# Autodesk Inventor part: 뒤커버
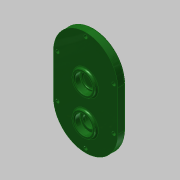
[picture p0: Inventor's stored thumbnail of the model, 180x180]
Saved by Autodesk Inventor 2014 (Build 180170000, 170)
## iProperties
Created: 2016-12
Part Number: 뒤커버
Material: 일반
Document SubType Name: Modeling
Designer: mduedu
Density: 1 g/cm^3
Appearance: 매끄러움 - 짙은 산림 녹색
Mass: 87.2081 g
Surface Area: 240.959 cm^2
Volume: 87.2081 cm^3
Author: mduedu
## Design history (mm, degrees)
sketch "스케치1"
  geometry: L1 (40, -25)-(40, 25); L2 (-40, 25)-(-40, -25); L3 (-40, -25)-(40, 25); L4 (40, -25)-(-40, 25); A1 r 40 centre (0, 25) between (40, 25) and (-40, 25); A2 r 40 centre (0, -25) between (-40, -25) and (40, -25); 1 further point
  constraints: 8 end point, 4 point on circle, 4 tangent, 2 centre point, 2 midpoint, 1 parallel, 1 vertical
  dimensions: "d0" = 130 dimension on A2 A1; "d2" = 80 distance between parallel lines of L1 L2
extrude "돌출1" new body sketch "스케치1" distance "d3" = 10; taper "d4" = 0 deg
sketch "스케치2"
  geometry: C1 r 14 at (0, 11); 1 further point
  constraints: 1 centre point, 1 vertical alignment
  dimensions: "d5" = 28 diameter of C1; "d6" = 11 distance of C1.centre point (0, 0)
extrude "돌출2" join sketch "스케치2" distance "d7" = 3; taper "d8" = 0 deg
sketch "스케치3"
  geometry: C1 r 14 at (0, -33.1); C2 r 14 at (0, 11) reference; 1 further point
  constraints: 1 centre point, 1 vertical alignment
  dimensions: "d9" = 28 diameter of C1; "d69" = 44.1 distance of C1.centre C2.centre
extrude "돌출3" join sketch "스케치3" distance "d11" = 3; taper "d12" = 0 deg
hole "구멍1" diameter "d15" = 22; stored, may be unused: countersink angle "d19" = 90 deg, drill point angle "d21" = 0 deg; dims "d13" = 10, "d14" = 10, "d16" = 6, "d17" = 4, "d18" = 2, "d20" = 7
hole "구멍2" diameter "d24" = 18; stored, may be unused: countersink angle "d28" = 90 deg, drill point angle "d30" = 0 deg; dims "d22" = 10, "d23" = 10, "d25" = 6, "d26" = 4, "d27" = 2, "d29" = 1
hole "구멍3" diameter "d33" = 22; stored, may be unused: countersink angle "d37" = 90 deg, drill point angle "d39" = 0 deg; dims "d31" = 10, "d32" = 10, "d34" = 6, "d35" = 4, "d36" = 2, "d38" = 7
sketch "스케치4"
  geometry: C1 r 14 at (0, -33.1) reference; C2 r 18 at (0, -33.1); 1 further point
  constraints: 1 centre point, 1 coincident
  dimensions: "d40" = 36 diameter of C2
extrude "돌출4" join sketch "스케치4" distance "d41" = 4; taper "d42" = 0 deg
hole "구멍4" diameter "d45" = 22; stored, may be unused: countersink angle "d49" = 90 deg, drill point angle "d51" = 0 deg; dims "d46" = 6, "d47" = 4, "d48" = 2, "d50" = 7.3, "d80" = 10, "d81" = 10
hole "구멍5" diameter "d54" = 15; stored, may be unused: countersink angle "d58" = 90 deg, drill point angle "d60" = 0 deg; dims "d52" = 10, "d53" = 10, "d55" = 6, "d56" = 4, "d57" = 2, "d59" = 7
fillet "모깎기1" dims "d61" = 0.3
fillet "모깎기2" dims "d62" = 2
chamfer "모따기1" distance "d63" = 1; stored, may be unused: second distance "d64" = 2, angle "d65" = 45 deg
chamfer "모따기2" distance "d82" = 0.7; stored, may be unused: second distance "d83" = 2, angle "d84" = 30 deg
fillet "모깎기3" dims "d66" = 2
fillet "모깎기4" dims "d67" = 2
fillet "모깎기5" dims "d68" = 2
sketch "스케치5"
  geometry: L1 (-40, 25)-(-40, -25) reference; L2 (40, -25)-(40, 25) reference; L3 (35, 25)-(35, -25); L4 (-35, -25)-(-35, 25); A1 r 40 centre (0, 25) between (40, 25) and (-40, 25) reference; A2 r 40 centre (0, -25) between (-40, -25) and (40, -25) reference; A3 r 35 centre (0, 25) between (35, 25) and (-35, 25); A4 r 35 centre (0, -25) between (-35, -25) and (35, -25); 2 further points
  constraints: 5 point on circle, 4 end point, 2 centre point, 1 vertical alignment, 3 other
  dimensions: "d70" = 5 distance between parallel lines of L2 L3
sketch "스케치6"
  geometry: 1 further point
  constraints: 1 other
hole "구멍6" sketch "스케치6" at (0, 60) diameter "d71" = 4.5; stored, may be unused: countersink angle "d75" = 90 deg, drill point angle "d77" = 0 deg; dims "d72" = 6, "d73" = 8, "d74" = 4.6, "d76" = 8
node "솔리드1"
pattern_linear "직사각형 패턴1"
